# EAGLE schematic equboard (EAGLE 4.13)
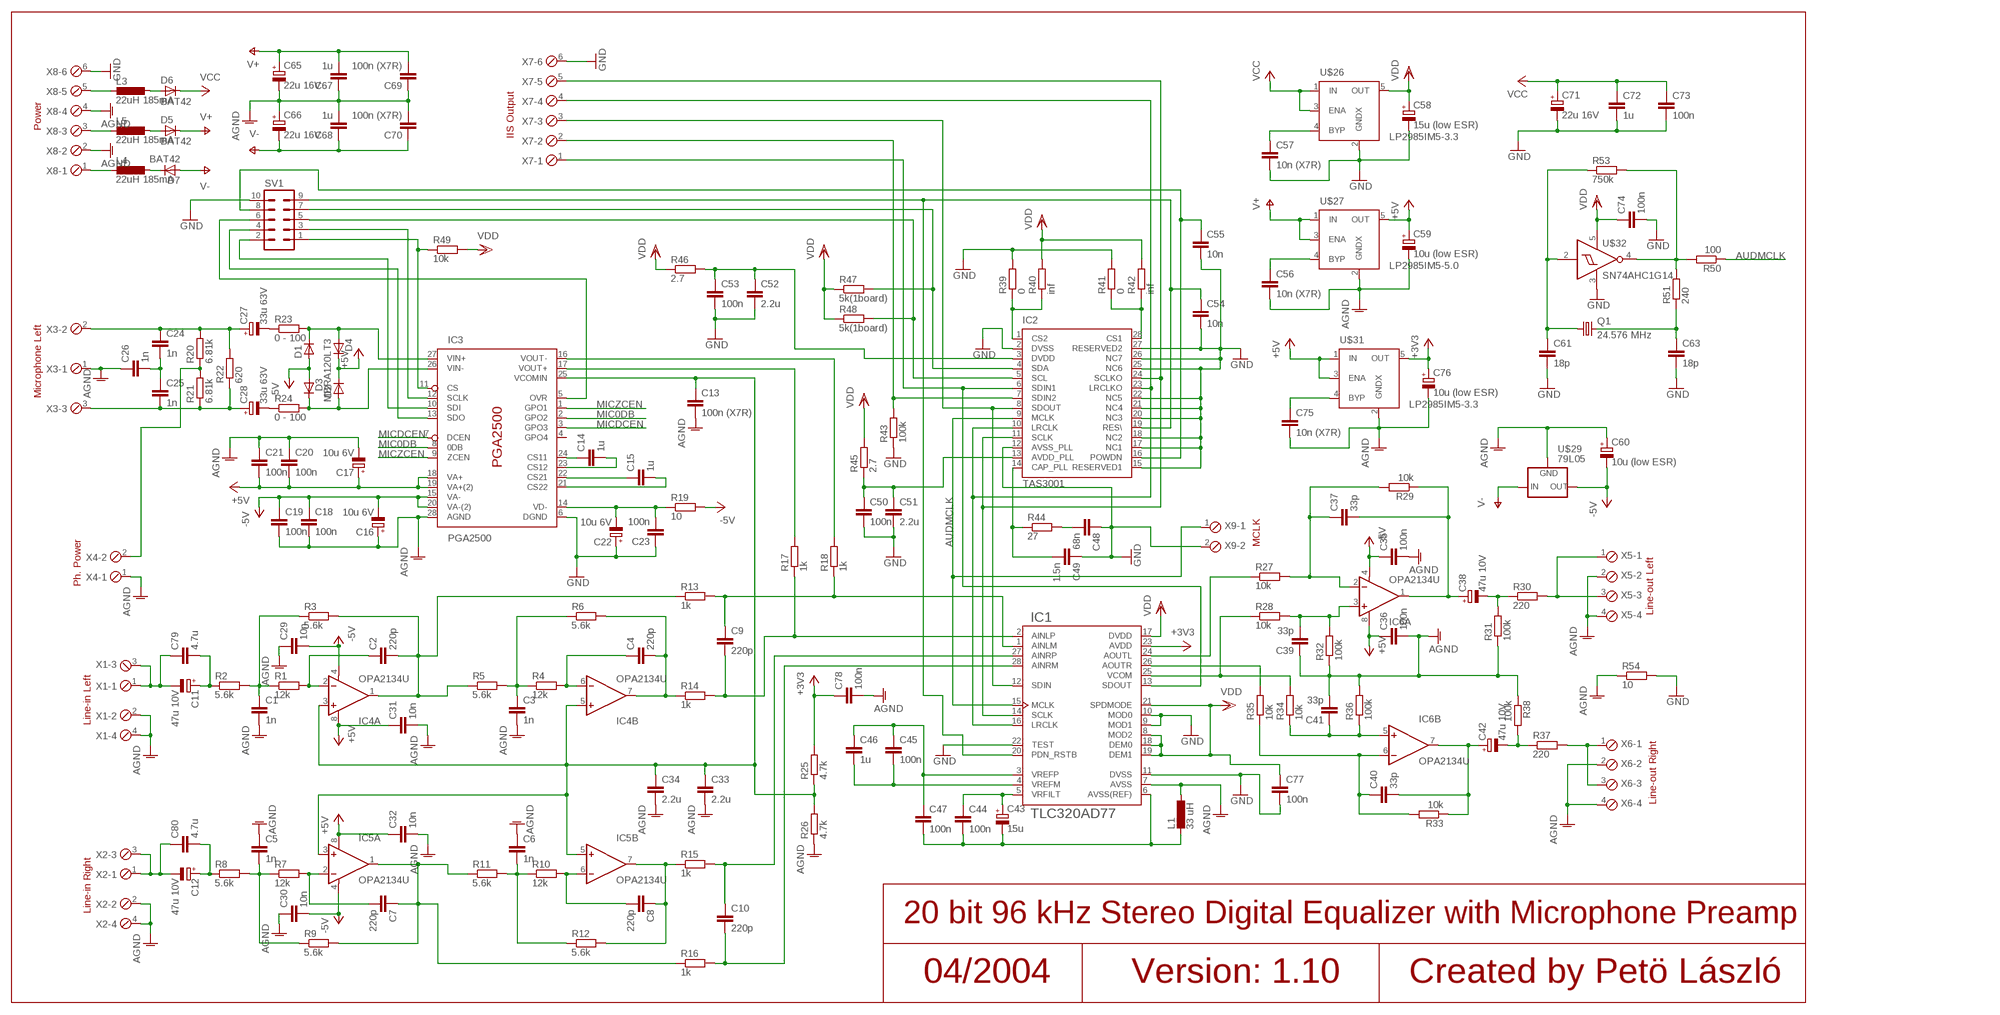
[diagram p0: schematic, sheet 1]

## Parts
C1  1n  C-0805  [C0805]
C2  220p  C-0805  [C0805]
C3  1n  C-0805  [C0805]
C4  220p  C-0805  [C0805]
C5  1n  C-0805  [C0805]
C6  1n  C-0805  [C0805]
C7  220p  C-0805  [C0805]
C8  220p  C-0805  [C0805]
C9  220p  C-0805  [C0805]
C10  220p  C-0805  [C0805]
C11  47u 10V  CPOL-EU153CLV-0505  [153CLV-0505]
C12  47u 10V  CPOL-EU153CLV-0505  [153CLV-0505]
C13  100n (X7R)  C-0805  [C0805]
C14  1u  C-0805  [C0805]
C15  1u  C-0805  [C0805]
C16  10u 6V  CPOL-EU153CLV-0405  [153CLV-0405]
C17  10u 6V  CPOL-EU153CLV-0405  [153CLV-0405]
C18  100n  C-0805  [C0805]
C19  100n  C-0805  [C0805]
C20  100n  C-0805  [C0805]
C21  100n  C-0805  [C0805]
C22  10u 6V  CPOL-EU153CLV-0405  [153CLV-0405]
C23  100n  C-0805  [C0805]
C24  1n  C-0805  [C0805]
C25  1n  C-0805  [C0805]
C26  1n  C-0805  [C0805]
C27  33u 63V  CPOL-EU153CLV-0605  [153CLV-0605]
C28  33u 63V  CPOL-EU153CLV-0605  [153CLV-0605]
C29  10n  C-0805  [C0805]
C30  10n  C-0805  [C0805]
C31  10n  C-0805  [C0805]
C32  10n  C-0805  [C0805]
C33  2.2u  C-0805  [C0805]
C34  2.2u  C-0805  [C0805]
C35  100n  C-0805  [C0805]
C36  100n  C-0805  [C0805]
C37  33p  C-0805  [C0805]
C38  47u 10V  CPOL-EU153CLV-0505  [153CLV-0505]
C39  33p  C-0805  [C0805]
C40  33p  C-0805  [C0805]
C41  33p  C-0805  [C0805]
C42  47u 10V  CPOL-EU153CLV-0505  [153CLV-0505]
C43  15u  CPOL-EU153CLV-0405  [153CLV-0405]
C44  100n  C-0805  [C0805]
C45  100n  C-0805  [C0805]
C46  1u  C-0805  [C0805]
C47  100n  C-0805  [C0805]
C48  68n  C-0805  [C0805]
C49  1.5n  C-0805  [C0805]
C50  100n  C-0805  [C0805]
C51  2.2u  C-0805  [C0805]
C52  2.2u  C-0805  [C0805]
C53  100n  C-0805  [C0805]
C54  10n  C-0805  [C0805]
C55  10n  C-0805  [C0805]
C56  10n (X7R)  C-0805  [C0805]
C57  10n (X7R)  C-0805  [C0805]
C58  15u (low ESR)  CPOL-EU153CLV-0405  [153CLV-0405]
C59  10u (low ESR)  CPOL-EU153CLV-0405  [153CLV-0405]
C60  10u (low ESR)  CPOL-EU153CLV-0405  [153CLV-0405]
C61  18p  C-0805  [C0805]
C63  18p  C-0805  [C0805]
C65  22u 16V  CPOL-EU153CLV-0505  [153CLV-0505]
C66  22u 16V  CPOL-EU153CLV-0505  [153CLV-0505]
C67  1u  C-0805  [C0805]
C68  1u  C-0805  [C0805]
C69  100n (X7R)  C-0805  [C0805]
C70  100n (X7R)  C-0805  [C0805]
C71  22u 16V  CPOL-EU153CLV-0505  [153CLV-0505]
C72  1u  C-0805  [C0805]
C73  100n  C-0805  [C0805]
C74  100n  C-0805  [C0805]
C75  10n (X7R)  C-0805  [C0805]
C76  10u (low ESR)  CPOL-EU153CLV-0405  [153CLV-0405]
C77  100n  C-0805  [C0805]
C78  100n  C-0805  [C0805]
C79  4.7u  C-EUC1206  [C1206]
C80  4.7u  C-EUC1206  [C1206]
D1  D-SMB  [SMB]
D2  D-SMB  [SMB]
D3  D-SMB  [SMB]
D4  MBRA120LT3  D-SMB  [SMB]
D5  BAT42  D-SOD-80  [SOD80]
D6  BAT42  D-SOD-80  [SOD80]
D7  BAT42  D-SOD-80  [SOD80]
IC1  TLC320AD77  [SSOP28DB]
IC2  TAS3001  [PSO28]
IC3  PGA2500  [SSOP28DB]
IC4  OPA2134U  [SO08]
IC5  OPA2134U  [SO08]
IC6  OPA2134U  [SO08]
L1  33 uH  L-EUL5038P  [L5038P]
L3  22uH 185mA  L-EUL4532C  [L4532M]
L4  22uH 185mA  L-EUL4532C  [L4532M]
L5  22uH 185mA  L-EUL4532C  [L4532M]
Q1  24.576 MHz  CRYTALHC49S  [HC49/S]
R1  12k  R-0805  [R0805]
R2  5.6k  R-0805  [R0805]
R3  5.6k  R-0805  [R0805]
R4  12k  R-0805  [R0805]
R5  5.6k  R-0805  [R0805]
R6  5.6k  R-0805  [R0805]
R7  12k  R-0805  [R0805]
R8  5.6k  R-0805  [R0805]
R9  5.6k  R-0805  [R0805]
R10  12k  R-0805  [R0805]
R11  5.6k  R-0805  [R0805]
R12  5.6k  R-0805  [R0805]
R13  1k  R-0805  [R0805]
R14  1k  R-0805  [R0805]
R15  1k  R-0805  [R0805]
R16  1k  R-0805  [R0805]
R17  1k  R-0805  [R0805]
R18  1k  R-0805  [R0805]
R19  10  R-0805  [R0805]
R20  6.81k  R-EU_R1206  [R1206]
R21  6.81k  R-EU_R1206  [R1206]
R22  620  R-0805  [R0805]
R23  0 - 100  R-0805  [R0805]
R24  0 - 100  R-0805  [R0805]
R25  4.7k  R-0805  [R0805]
R26  4.7k  R-0805  [R0805]
R27  10k  R-0805  [R0805]
R28  10k  R-0805  [R0805]
R29  10k  R-0805  [R0805]
R30  220  R-0805  [R0805]
R31  100k  R-0805  [R0805]
R32  100k  R-0805  [R0805]
R33  10k  R-0805  [R0805]
R34  10k  R-0805  [R0805]
R35  10k  R-0805  [R0805]
R36  100k  R-0805  [R0805]
R37  220  R-0805  [R0805]
R38  100k  R-0805  [R0805]
R39  0  R-0805  [R0805]
R40  inf  R-0805  [R0805]
R41  0  R-0805  [R0805]
R42  inf  R-0805  [R0805]
R43  100k  R-0805  [R0805]
R44  27  R-0805  [R0805]
R45  2.7  R-0805  [R0805]
R46  2.7  R-0805  [R0805]
R47  5k(1board)  R-0805  [R0805]
R48  5k(1board)  R-0805  [R0805]
R49  10k  R-0805  [R0805]
R50  100  R-0805  [R0805]
R51  240  R-0805  [R0805]
R53  750k  R-0805  [R0805]
R54  10  R-0805  [R0805]
SV1  MA05-2  [MA05-2]
U$26  LP2985IM5-3.3  [SOT23-5]
U$27  LP2985IM5-5.0  [SOT23-5]
U$29  79L05  [SOT89R]
U$31  LP2985IM5-3.3  [SOT23-5]
U$32  SN74AHC1G14  [SOT23-5]
X1  MPT4  [4POL254]
X2  MPT4  [4POL254]
X3  MPT3  [3POL254]
X4  MPT2  [2POL254]
X5  MPT4  [4POL254]
X6  MPT4  [4POL254]
X7  MPT6  [6POL254]
X8  MPT6  [6POL254]
X9  MPT2  [2POL254]

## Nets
+3V3: C76.+ C78.1 IC1.23(AVDD) R25.2 U$31.5(OUT)
+5V: C17.+ C20.2 C21.2 C31.1 C32.1 C36.1 C59.+ D2.1(C) D4.1(C) IC3.18(VA+) IC3.19(VA+(2)) IC4.8(A:VA+) IC5.8(A:VA+) IC6.8(A:VA+) U$27.5(OUT) U$31.1(IN) U$31.3(ENA)
-5V: C16.- C18.1 C19.1 C29.2 C30.2 C35.1 C60.- D1.2(A) D3.2(A) IC3.15(VA-) IC3.20(VA-(2)) IC4.4(A:VA-) IC5.4(A:VA-) IC6.4(A:VA-) R19.2 U$29.3(OUT)
AGND: C1.2 C3.2 C5.1 C6.1 C13.2 C16.+ C17.- C18.2 C19.2 C20.1 C21.1 C26.1 C29.1 C30.1 C31.2 C32.2 C33.2 C34.2 C35.2 C36.2 C39.1 C41.2 C56.2 C59.- C60.+ C65.- C66.+ C67.1 C68.2 C69.1 C70.2 C75.2 C76.- C78.2 IC1.7(AVSS) IC3.28(AGND) L1.1 R26.1 R31.1 R32.1 R36.2 R38.1 R54.1 U$27.2(GNDX) U$29.1(GNDX) U$31.2(GNDX) X1.2 X1.4 X2.2 X2.4 X3.1 X4.1 X5.2 X5.4 X6.2 X6.4 X8.2 X8.4
AUDMCLK: IC1.15(MCLK) IC2.9(MCLK) R50.1 X9.1
GND: C22.+ C23.1 C48.1 C49.1 C50.2 C51.2 C52.2 C53.2 C54.2 C55.2 C57.2 C58.- C61.2 C63.2 C71.- C72.2 C73.2 C74.2 C77.2 IC1.9(MOD1) IC1.10(MOD0) IC1.11(DVSS) IC1.22(TEST) IC2.2(DVSS) IC2.12(AVSS_PLL) IC2.15(RESERVED1) IC2.17(NC1) IC2.18(NC2) IC2.20(NC3) IC2.21(NC4) IC2.22(NC5) IC2.25(NC6) IC2.26(NC7) IC2.27(RESERVED2) IC3.6(DGND) R39.2 R41.2 R43.1 R54.2 SV1.10 U$26.2(GNDX) U$32.3(GNDX) X7.6 X8.6 X9.2
MIC0DB: IC3.2(GPO2) IC3.8(0DB)
MICDCEN: IC3.3(GPO3) IC3.7(DCEN)
MICZCEN: IC3.1(GPO1) IC3.9(ZCEN)
N$3: C1.1 R1.1 R2.2 R3.1
N$4: C2.1 IC4.2(A:-IN) R1.2
N$5: C2.2 IC4.1(A:OUT) R3.2 R5.1 R13.1
N$6: C3.1 R4.1 R5.2 R6.1
N$7: C4.1 IC4.6(B:-IN) R4.2
N$8: C9.1 IC1.1(AINLM) R13.2 R18.1
N$9: C5.2 R7.1 R8.2 R9.1
N$10: IC1.24(AOUTL) R27.1
N$11: C7.2 IC5.2(A:-IN) R7.2
N$12: C7.1 IC5.1(A:OUT) R9.2 R11.1 R16.1
N$13: C6.2 R10.1 R11.2 R12.1
N$14: C9.2 IC1.2(AINLP) R14.2 R17.1
N$15: C8.2 IC5.6(B:-IN) R10.2
N$16: C4.2 IC4.7(B:OUT) R6.2 R14.1
N$17: C8.1 IC5.7(B:OUT) R12.2 R15.1
N$18: C10.1 IC1.27(AINRP) R15.2
N$19: C10.2 IC1.28(AINRM) R16.2
N$20: C11.+ C79.2 R2.1
N$21: C12.+ C80.2 R8.1
N$22: IC3.16(VOUT-) R18.2
N$23: IC3.17(VOUT+) R17.2
N$24: C11.- C79.1 X1.1 X1.3
N$25: C12.- C80.1 X2.1 X2.3
N$26: C14.1 IC3.24(CS11)
N$27: C15.1 IC3.22(CS21)
N$28: C14.2 IC3.23(CS12)
N$29: C15.2 IC3.21(CS22)
N$30: C22.- C23.2 IC3.14(VD-) R19.1
N$31: C56.1 U$27.4(BYP)
N$32 [Phantom]: C25.2 C28.+ R21.1 R22.1 X3.3
N$33 [Phantom]: C24.2 C25.1 C26.2
N$34 [Phantom]: C24.1 C27.+ R20.2 R22.2 X3.2
N$35: C13.1 C33.1 C34.1 IC3.25(VCOMIN) IC4.3(A:+IN) IC4.5(B:+IN) IC5.3(A:+IN) IC5.5(B:+IN) R25.1 R26.2
N$36: C27.- R23.1
N$37: C28.- R24.1
N$38: D1.1(C) D4.2(A) IC3.27(VIN+) R23.2
N$39: D2.2(A) D3.1(C) IC3.26(VIN-) R24.2
N$40: IC3.11(CS) R49.1 SV1.1
N$41: IC1.25(VCOM) R28.1 R34.2
N$42: C37.1 IC6.2(A:-IN) R27.2 R29.2
N$43: C39.2 IC6.3(A:+IN) R28.2 R32.2
N$44: C37.2 C38.+ IC6.1(A:OUT) R29.1
N$45: C38.- R30.1 R31.2
N$46: R30.2 X5.1 X5.3
N$47: IC1.26(AOUTR) R35.2
N$48: C41.1 IC6.5(B:+IN) R34.1 R36.1
N$49: C40.1 IC6.6(B:-IN) R33.2 R35.1
N$50: C43.+ C44.1 IC1.5(VRFILT)
N$51: C40.2 C42.+ IC6.7(B:OUT) R33.1
N$52: C42.- R37.1 R38.2
N$53: R37.2 X6.1 X6.3
N$54: C43.- C44.2 C47.2 IC1.6(AVSS(REF)) L1.2
N$55: C45.2 C46.2 IC1.4(VREFM)
N$56: IC2.1(CS2) R39.1 R40.1
N$57: C45.1 C46.1 C47.1 IC1.3(VREFP)
N$58: IC2.28(CS1) R41.1 R42.1
N$59: L3.2 X8.5
N$60: L5.2 X8.3
N$61: IC1.12(SDIN) IC2.8(SDOUT) X7.3
N$62: IC1.14(SCLK) IC2.11(SCLK) IC2.24(SCLKO) X7.5
N$63: IC1.16(LRCLK) IC2.10(LRCLK) IC2.23(LRCLKO) X7.4
N$64: IC1.13(SDOUT) IC2.6(SDIN1) X7.1
N$65: C55.1 IC2.16(POWDN) SV1.8
N$66: IC2.7(SDIN2) R43.2 X7.2
N$67: IC2.4(SDA) R47.2 SV1.7
N$68: IC2.5(SCL) R48.2 SV1.5
N$69: C49.2 IC2.14(CAP_PLL) R44.1
N$70: C48.2 R44.2
N$71: C63.1 Q1.2 R51.1
N$72 [Phantom]: R20.1 R21.2 X4.2
N$73: C50.1 C51.1 IC2.13(AVDD_PLL) R45.1
N$74: IC3.12(SCLK) SV1.3
N$75: IC3.10(SDI) SV1.2
N$76: IC3.13(SDO) SV1.4
N$77: C54.1 IC1.20(PDN_RSTB) IC2.19(RES\) SV1.9
N$78: IC3.5(OVR) SV1.6
N$79: C61.1 Q1.1 R53.1 U$32.2(A)
N$80: C57.1 U$26.4(BYP)
N$84: R50.2 R51.2 R53.2 U$32.4(Y)
N$85: L4.2 X8.1
N$86: C52.1 C53.1 IC2.3(DVDD) R46.2
N$87: C75.1 U$31.4(BYP)
N$88: D6.2(A) L3.1
N$89: D7.1(C) L4.1
N$90: D5.2(A) L5.1
V+: C65.+ C67.2 C69.2 D5.1(C) U$27.1(IN) U$27.3(ENA)
V-: C66.- C68.1 C70.1 D7.2(A) U$29.2(IN)
VCC: C71.+ C72.1 C73.1 D6.1(C) U$26.1(IN) U$26.3(ENA)
VDD: C58.+ C74.1 C77.1 IC1.8(MOD2) IC1.17(DVDD) IC1.18(DEM0) IC1.19(DEM1) IC1.21(SPDMODE) R40.2 R42.2 R45.2 R46.1 R47.1 R48.1 R49.2 U$26.5(OUT) U$32.5(VDDX)
Unconnected: IC3.4(GPO4)

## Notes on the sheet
- IIS Output
- Power
- Microphone Left
- MCLK
- Line-out Left
- Ph. Power
- Line-in Left
- Line-out Right
- Line-in Right
- 20 bit 96 kHz Stereo Digital Equalizer with Microphone Preamp
- 04/2004 | Version: 1.10 | Created by Petö László

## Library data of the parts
C1-C10 C13-C15 C18-C21 C23-C26 C29-C37 C39-C41 C44-C57 C61 C63 C67-C70 C72-C75 C77 C78 = digiaudio:C-0805: 0805 SMD CAPACITOR
C11 C12 C16 C17 C22 C27 C28 C38 C42 C43 C58-C60 C65 C66 C71 C76 = rcl:CPOL-EU: POLARIZED CAPACITOR, European symbol
C79 C80 = rcl:C-EU: CAPACITOR, European symbol
D1-D7 = semicon-smd-ipc:D-: DIODE
IC1 = digiaudio:TLC320AD77: 24 bit 96 kHz Audio Codec
IC2 = digiaudio:TAS3001: TAS3001C Digital Audio Processor
IC3 = digiaudio:PGA2500: Digitally Controlled Microphone Preamplifier
IC4-IC6 = digiaudio:OPA2134: Operational Amplifier
L1 L3-L5 = rcl:L-EU: INDUCTOR, European symbol
Q1 = crystal:CRYTAL: CRYSTAL
R1-R19 R22-R51 R53 R54 = digiaudio:R-0805: 0805 SMD RESISTOR
R20 R21 = rcl:R-EU_: RESISTOR, European symbol
SV1 = con-lstb:MA05-2: PIN HEADER
U$26 U$31 = digiaudio:LP2985IM5-3.3: Low Noise Voltage Regulator
U$27 = digiaudio:LP2985IM5-5.0: Low Noise Voltage Regulator
U$29 = digiaudio:79L05: Negative Voltage Regulator
U$32 = digiaudio:SN74AHC1G14: Single Schmitt-trigger Inverter Gate
X1 X2 X5 X6 = con-phoenix-254:MPT4: PHOENIX CONNECTOR
X3 = con-phoenix-254:MPT3: PHOENIX CONNECTOR
X4 X9 = con-phoenix-254:MPT2: PHOENIX CONNECTOR
X7 X8 = con-phoenix-254:MPT6: PHOENIX CONNECTOR

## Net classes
1 Phantom: drill 0.711 mm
